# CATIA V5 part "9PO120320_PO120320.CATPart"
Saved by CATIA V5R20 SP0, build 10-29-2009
Part number: 9PO120320_PO120320
Revision: ANY
Definition: UNKNOWN
Nomenclature: 9PO120320_PO120320
Source: Unknown
Bounding box of the stored display mesh (mm): x -2.853 to 2.853, y 0 to 11.6, z -3 to 3
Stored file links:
  C:\Users\Utente\Desktop\IO LAVORO\3D X SITO CF\CUMSA\3D files PO\PO 120320\9PO120320_PO120320.CATPart
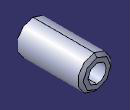
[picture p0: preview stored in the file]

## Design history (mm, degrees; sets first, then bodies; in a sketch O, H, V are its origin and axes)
Body1 "Chaflán2" (main body)
  Solid1: solid without history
